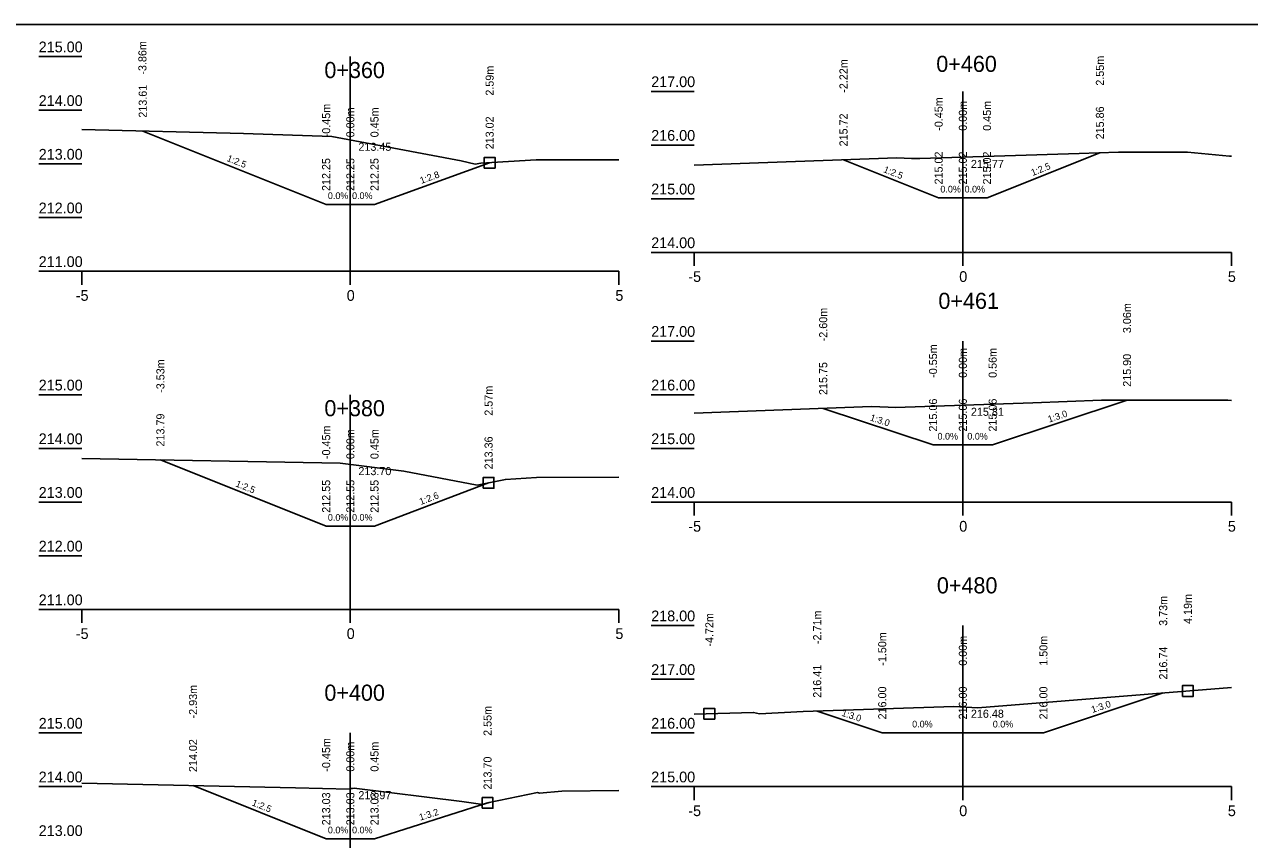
# Model space of a CAD drawing. Extents: x -577315 to -577212, y -1159820 to -1159790.
# Drawn here: x -577267.41 to -577244.61, y -1159805.53 to -1159790.35 of the extents above; entities that cross this region are included whole.
import ezdxf

# ---------------------------------------------------------------- set-up
doc = ezdxf.new("R2010")
doc.units = 0
for name, color, linetype in [('16', 7, 'Continuous'), ('21', 7, 'Continuous'), ('28', 7, 'Continuous'), ('59', 7, 'Continuous'), ('Body pricny rez', 7, 'Continuous'), ('Hranice_pozemku', 7, 'Continuous'), ('Popis pricneho profilu', 7, 'Continuous'), ('Rámy', 7, 'Continuous')]:
    doc.layers.add(name, color=color, linetype=linetype)

msp = doc.modelspace()

# ---------------------------------------------------------------- linework, layer by layer
for points in [[(-577266.343, -1159792.31), (-577263.333, -1159792.381), (-577261.685, -1159792.439), (-577259.281, -1159792.891), (-577259.018, -1159792.954), (-577258.911, -1159792.937), (-577257.886, -1159792.874), (-577257.387, -1159792.874), (-577256.343, -1159792.871)], [(-577261.793, -1159793.703), (-577265.207, -1159792.337)], [(-577254.943, -1159792.973), (-577251.17, -1159792.836), (-577250.9, -1159792.846), (-577250.745, -1159792.85), (-577247.777, -1159792.754), (-577247.043, -1159792.729), (-577245.762, -1159792.728), (-577244.982, -1159792.802), (-577244.943, -1159792.803)], [(-577250.393, -1159793.581), (-577252.164, -1159792.872)], [(-577249.493, -1159793.581), (-577247.392, -1159792.741)], [(-577260.893, -1159793.703), (-577258.75, -1159792.927)], [(-577250.393, -1159793.581), (-577249.943, -1159793.581), (-577249.493, -1159793.581)], [(-577261.793, -1159793.703), (-577261.343, -1159793.703), (-577260.893, -1159793.703)], [(-577254.943, -1159797.593), (-577251.641, -1159797.469), (-577251.331, -1159797.48), (-577251.195, -1159797.483), (-577248.638, -1159797.397), (-577247.363, -1159797.351), (-577245.009, -1159797.348), (-577244.943, -1159797.354)], [(-577249.388, -1159798.184), (-577246.887, -1159797.35)], [(-577250.498, -1159798.184), (-577252.542, -1159797.503)], [(-577250.498, -1159798.184), (-577249.943, -1159798.184), (-577249.388, -1159798.184)], [(-577266.343, -1159798.438), (-577261.533, -1159798.522), (-577260.348, -1159798.675), (-577258.98, -1159798.931), (-577258.455, -1159798.827), (-577257.878, -1159798.791), (-577256.343, -1159798.787)], [(-577261.793, -1159799.697), (-577264.878, -1159798.463)], [(-577260.893, -1159799.697), (-577258.77, -1159798.889)], [(-577261.793, -1159799.697), (-577261.343, -1159799.697), (-577260.893, -1159799.697)], [(-577254.943, -1159803.199), (-577253.838, -1159803.168), (-577253.727, -1159803.195), (-577252.913, -1159803.152), (-577250.109, -1159803.059), (-577249.666, -1159803.079), (-577244.943, -1159802.703)], [(-577248.443, -1159803.547), (-577246.214, -1159802.804)], [(-577251.443, -1159803.547), (-577252.654, -1159803.143)], [(-577251.443, -1159803.547), (-577249.943, -1159803.547), (-577248.443, -1159803.547)], [(-577266.343, -1159804.482), (-577262.363, -1159804.571), (-577261.358, -1159804.594), (-577261.347, -1159804.583), (-577261.332, -1159804.583), (-577261.301, -1159804.583), (-577261.269, -1159804.575), (-577259.268, -1159804.825), (-577258.918, -1159804.878), (-577258.912, -1159804.892), (-577258.9, -1159804.887), (-577258.76, -1159804.844), (-577257.859, -1159804.661), (-577257.82, -1159804.672), (-577257.409, -1159804.636), (-577256.343, -1159804.624)], [(-577261.793, -1159805.52), (-577264.271, -1159804.528)], [(-577260.893, -1159805.52), (-577258.789, -1159804.853)], [(-577261.793, -1159805.52), (-577261.343, -1159805.52), (-577260.893, -1159805.52)]]:
    msp.add_lwpolyline(points)
at = {"layer": '16'}
for p, q in [((-577254.943, -1159794.597), (-577244.943, -1159794.597)), ((-577266.343, -1159794.949), (-577256.343, -1159794.949)), ((-577254.943, -1159799.249), (-577244.943, -1159799.249)), ((-577266.343, -1159801.249), (-577256.343, -1159801.249)), ((-577254.943, -1159804.549), (-577244.943, -1159804.549))]:
    msp.add_line(p, q, dxfattribs=at)
at = {"layer": '21'}
for p, q in [((-577267.143, -1159790.949), (-577266.343, -1159790.949)), ((-577255.743, -1159791.597), (-577254.943, -1159791.597)), ((-577267.143, -1159791.949), (-577266.343, -1159791.949)), ((-577255.743, -1159792.597), (-577254.943, -1159792.597)), ((-577267.143, -1159792.949), (-577266.343, -1159792.949)), ((-577255.743, -1159793.597), (-577254.943, -1159793.597)), ((-577267.143, -1159793.949), (-577266.343, -1159793.949)), ((-577255.743, -1159794.597), (-577254.943, -1159794.597)), ((-577267.143, -1159794.949), (-577266.343, -1159794.949)), ((-577255.743, -1159796.249), (-577254.943, -1159796.249)), ((-577267.143, -1159797.249), (-577266.343, -1159797.249)), ((-577255.743, -1159797.249), (-577254.943, -1159797.249)), ((-577267.143, -1159798.249), (-577266.343, -1159798.249)), ((-577255.743, -1159798.249), (-577254.943, -1159798.249)), ((-577267.143, -1159799.249), (-577266.343, -1159799.249)), ((-577255.743, -1159799.249), (-577254.943, -1159799.249)), ((-577267.143, -1159800.249), (-577266.343, -1159800.249)), ((-577267.143, -1159801.249), (-577266.343, -1159801.249)), ((-577255.743, -1159801.549), (-577254.943, -1159801.549)), ((-577255.743, -1159802.549), (-577254.943, -1159802.549)), ((-577267.143, -1159803.549), (-577266.343, -1159803.549)), ((-577255.743, -1159803.549), (-577254.943, -1159803.549)), ((-577267.143, -1159804.549), (-577266.343, -1159804.549)), ((-577255.743, -1159804.549), (-577254.943, -1159804.549))]:
    msp.add_line(p, q, dxfattribs=at)
at = {"layer": '28'}
for p, q in [((-577261.343, -1159790.949), (-577261.343, -1159794.949)), ((-577249.943, -1159791.597), (-577249.943, -1159794.597)), ((-577249.943, -1159796.249), (-577249.943, -1159799.249)), ((-577261.343, -1159797.249), (-577261.343, -1159801.249)), ((-577249.943, -1159801.549), (-577249.943, -1159804.549)), ((-577261.343, -1159803.549), (-577261.343, -1159806.549))]:
    msp.add_line(p, q, dxfattribs=at)
at = {"layer": '59'}
for p, q in [((-577254.943, -1159794.847), (-577254.943, -1159794.597)), ((-577249.943, -1159794.847), (-577249.943, -1159794.597)), ((-577244.943, -1159794.847), (-577244.943, -1159794.597)), ((-577266.343, -1159795.199), (-577266.343, -1159794.949)), ((-577261.343, -1159795.199), (-577261.343, -1159794.949)), ((-577256.343, -1159795.199), (-577256.343, -1159794.949)), ((-577254.943, -1159799.499), (-577254.943, -1159799.249)), ((-577249.943, -1159799.499), (-577249.943, -1159799.249)), ((-577244.943, -1159799.499), (-577244.943, -1159799.249)), ((-577266.343, -1159801.499), (-577266.343, -1159801.249)), ((-577261.343, -1159801.499), (-577261.343, -1159801.249)), ((-577256.343, -1159801.499), (-577256.343, -1159801.249)), ((-577254.943, -1159804.799), (-577254.943, -1159804.549)), ((-577249.943, -1159804.799), (-577249.943, -1159804.549)), ((-577244.943, -1159804.799), (-577244.943, -1159804.549))]:
    msp.add_line(p, q, dxfattribs=at)
at = {"layer": 'Hranice_pozemku'}
for points in [[(-577258.85, -1159793.027), (-577258.65, -1159793.027), (-577258.65, -1159792.827), (-577258.85, -1159792.827)], [(-577258.87, -1159798.989), (-577258.67, -1159798.989), (-577258.67, -1159798.789), (-577258.87, -1159798.789)], [(-577245.855, -1159802.868), (-577245.655, -1159802.868), (-577245.655, -1159802.668), (-577245.855, -1159802.668)], [(-577254.761, -1159803.291), (-577254.561, -1159803.291), (-577254.561, -1159803.091), (-577254.761, -1159803.091)], [(-577258.889, -1159804.953), (-577258.689, -1159804.953), (-577258.689, -1159804.753), (-577258.889, -1159804.753)]]:
    msp.add_lwpolyline(points, close=True, dxfattribs=at)
at = {"layer": 'Rámy'}
msp.add_lwpolyline([(-577315.23, -1159790.351), (-577212.353, -1159790.351), (-577212.353, -1159820.051), (-577315.23, -1159820.051)], close=True, dxfattribs=at)

# ---------------------------------------------------------------- texts
for s, height, p in [('0+360', 0.3, (-577261.826, -1159791.349)), ('0+460', 0.3, (-577250.437, -1159791.234)), ('+', 0.001, (-577249.943, -1159793.582)), ('+', 0.001, (-577261.343, -1159793.703)), ('0+461', 0.3, (-577250.398, -1159795.649)), ('0+380', 0.3, (-577261.826, -1159797.649)), ('+', 0.001, (-577249.943, -1159798.184)), ('+', 0.001, (-577261.343, -1159799.698)), ('0+480', 0.3, (-577250.426, -1159800.949)), ('0+400', 0.3, (-577261.826, -1159802.949)), ('+', 0.001, (-577249.943, -1159803.548)), ('+', 0.001, (-577261.343, -1159805.52))]:
    msp.add_text(s, height=height).set_placement(p)
for s, rotation, p in [('1:2.5', 338.1986, (-577263.653, -1159792.891)), ('1:2.8', 19.9015, (-577260.021, -1159793.321)), ('1:2.5', 338.1986, (-577251.432, -1159793.098)), ('1:2.5', 21.8014, (-577248.643, -1159793.174)), ('1:3.0', 341.5651, (-577251.68, -1159797.724)), ('1:3.0', 18.4349, (-577248.337, -1159797.768)), ('1:2.5', 338.1986, (-577263.489, -1159798.952)), ('1:2.6', 20.8385, (-577260.031, -1159799.303)), ('1:3.0', 341.5651, (-577252.209, -1159803.226)), ('1:3.0', 18.4349, (-577247.528, -1159803.177)), ('1:2.5', 338.1986, (-577263.186, -1159804.895)), ('1:3.2', 17.5865, (-577260.041, -1159805.184))]:
    msp.add_text(s, height=0.125, rotation=rotation).set_placement(p)
at = {"layer": '16'}
for p in [(-577250.361, -1159793.481), (-577249.911, -1159793.481), (-577261.761, -1159793.603), (-577261.311, -1159793.603), (-577250.414, -1159798.084), (-577249.859, -1159798.084), (-577261.761, -1159799.597), (-577261.311, -1159799.597), (-577250.886, -1159803.447), (-577249.386, -1159803.447), (-577261.761, -1159805.42), (-577261.311, -1159805.42)]:
    msp.add_text('0.0%', height=0.125, rotation=360, dxfattribs=at).set_placement(p)
at = {"layer": '21'}
for s, p in [('215.00', (-577267.143, -1159790.869)), ('217.00', (-577255.743, -1159791.517)), ('214.00', (-577267.143, -1159791.869)), ('216.00', (-577255.743, -1159792.517)), ('213.00', (-577267.143, -1159792.869)), ('215.00', (-577255.743, -1159793.517)), ('212.00', (-577267.143, -1159793.869)), ('214.00', (-577255.743, -1159794.517)), ('211.00', (-577267.143, -1159794.869)), ('-5', (-577255.053, -1159795.147)), ('0', (-577250.01, -1159795.147)), ('5', (-577245.01, -1159795.147)), ('-5', (-577266.453, -1159795.499)), ('0', (-577261.41, -1159795.499)), ('5', (-577256.41, -1159795.499)), ('217.00', (-577255.743, -1159796.169)), ('215.00', (-577267.143, -1159797.169)), ('216.00', (-577255.743, -1159797.169)), ('214.00', (-577267.143, -1159798.169)), ('215.00', (-577255.743, -1159798.169)), ('213.00', (-577267.143, -1159799.169)), ('214.00', (-577255.743, -1159799.169)), ('-5', (-577255.053, -1159799.799)), ('0', (-577250.01, -1159799.799)), ('5', (-577245.01, -1159799.799)), ('212.00', (-577267.143, -1159800.169)), ('211.00', (-577267.143, -1159801.169)), ('218.00', (-577255.743, -1159801.469)), ('-5', (-577266.453, -1159801.799)), ('0', (-577261.41, -1159801.799)), ('5', (-577256.41, -1159801.799)), ('217.00', (-577255.743, -1159802.469)), ('215.00', (-577267.143, -1159803.469)), ('216.00', (-577255.743, -1159803.469)), ('214.00', (-577267.143, -1159804.469)), ('215.00', (-577255.743, -1159804.469)), ('-5', (-577255.053, -1159805.099)), ('0', (-577250.01, -1159805.099)), ('5', (-577245.01, -1159805.099)), ('213.00', (-577267.143, -1159805.469))]:
    msp.add_text(s, height=0.2, dxfattribs=at).set_placement(p)
at = {"layer": '59'}
for s, p in [('213.45', (-577261.193, -1159792.704)), ('215.77', (-577249.793, -1159793.024)), ('215.81', (-577249.793, -1159797.641)), ('213.70', (-577261.193, -1159798.746)), ('216.48', (-577249.793, -1159803.266)), ('213.97', (-577261.193, -1159804.783))]:
    msp.add_text(s, height=0.15, dxfattribs=at).set_placement(p)
at = {"layer": 'Body pricny rez'}
for p in [(-577265.207, -1159792.338), (-577252.165, -1159792.873), (-577247.393, -1159792.741), (-577258.75, -1159792.928), (-577250.393, -1159793.582), (-577249.493, -1159793.582), (-577261.793, -1159793.703), (-577260.893, -1159793.703), (-577246.887, -1159797.351), (-577252.542, -1159797.503), (-577250.498, -1159798.184), (-577249.388, -1159798.184), (-577264.878, -1159798.464), (-577258.77, -1159798.89), (-577261.793, -1159799.698), (-577260.893, -1159799.698), (-577246.215, -1159802.805), (-577252.655, -1159803.144), (-577251.443, -1159803.548), (-577248.443, -1159803.548), (-577264.272, -1159804.529), (-577258.79, -1159804.853), (-577261.793, -1159805.52), (-577260.893, -1159805.52)]:
    msp.add_text('+', height=0.001, dxfattribs=at).set_placement(p)
at = {"layer": 'Popis pricneho profilu'}
for s, p in [('-3.86m', (-577265.138, -1159791.285)), ('-2.22m', (-577252.089, -1159791.622)), ('2.55m', (-577247.317, -1159791.491)), ('2.59m', (-577258.675, -1159791.677)), ('2.59m', (-577258.675, -1159791.677)), ('2.59m', (-577258.675, -1159791.677)), ('213.61', (-577265.132, -1159792.087)), ('-0.45m', (-577250.318, -1159792.331)), ('-0.45m', (-577261.718, -1159792.453)), ('0.00m', (-577261.268, -1159792.453)), ('0.45m', (-577260.818, -1159792.453)), ('0.00m', (-577249.868, -1159792.331)), ('0.45m', (-577249.418, -1159792.331)), ('215.86', (-577247.317, -1159792.491)), ('213.02', (-577258.675, -1159792.677)), ('215.72', (-577252.089, -1159792.622)), ('212.25', (-577261.718, -1159793.453)), ('212.25', (-577261.268, -1159793.453)), ('212.25', (-577260.818, -1159793.453)), ('215.02', (-577250.318, -1159793.331)), ('215.02', (-577249.868, -1159793.331)), ('215.02', (-577249.418, -1159793.331)), ('-2.60m', (-577252.467, -1159796.253)), ('3.06m', (-577246.812, -1159796.1)), ('-0.55m', (-577250.423, -1159796.934)), ('0.00m', (-577249.868, -1159796.934)), ('0.56m', (-577249.313, -1159796.934)), ('215.90', (-577246.812, -1159797.1)), ('-3.53m', (-577264.803, -1159797.213)), ('215.75', (-577252.467, -1159797.253)), ('2.57m', (-577258.695, -1159797.639)), ('2.57m', (-577258.695, -1159797.639)), ('2.57m', (-577258.695, -1159797.639)), ('215.06', (-577250.423, -1159797.934)), ('215.06', (-577249.868, -1159797.934)), ('215.06', (-577249.313, -1159797.934)), ('213.79', (-577264.803, -1159798.213)), ('-0.45m', (-577261.718, -1159798.447)), ('0.00m', (-577261.268, -1159798.447)), ('0.45m', (-577260.818, -1159798.447)), ('213.36', (-577258.695, -1159798.639)), ('212.55', (-577261.718, -1159799.447)), ('212.55', (-577261.268, -1159799.447)), ('212.55', (-577260.818, -1159799.447)), ('3.73m', (-577246.139, -1159801.554)), ('4.19m', (-577245.68, -1159801.518)), ('4.19m', (-577245.68, -1159801.518)), ('-4.72m', (-577254.586, -1159801.941)), ('-4.72m', (-577254.586, -1159801.941)), ('-2.71m', (-577252.579, -1159801.893)), ('-1.50m', (-577251.368, -1159802.297)), ('0.00m', (-577249.868, -1159802.297)), ('1.50m', (-577248.368, -1159802.297)), ('216.74', (-577246.139, -1159802.554)), ('216.41', (-577252.579, -1159802.893)), ('-2.93m', (-577264.196, -1159803.278)), ('216.00', (-577251.368, -1159803.297)), ('216.00', (-577249.868, -1159803.297)), ('216.00', (-577248.368, -1159803.297)), ('2.55m', (-577258.714, -1159803.603)), ('2.55m', (-577258.714, -1159803.603)), ('2.55m', (-577258.714, -1159803.603)), ('214.02', (-577264.196, -1159804.278)), ('-0.45m', (-577261.718, -1159804.27)), ('0.00m', (-577261.268, -1159804.27)), ('0.45m', (-577260.818, -1159804.27)), ('213.70', (-577258.714, -1159804.603)), ('213.03', (-577261.718, -1159805.27)), ('213.03', (-577261.268, -1159805.27)), ('213.03', (-577260.818, -1159805.27))]:
    msp.add_text(s, height=0.15, rotation=90, dxfattribs=at).set_placement(p)

doc.saveas('drawing.dxf')
